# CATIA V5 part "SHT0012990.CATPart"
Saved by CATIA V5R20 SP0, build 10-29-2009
Part number: SHT0012990
Bounding box of the stored display mesh (mm): x 603.237 to 810.957, y -967.604 to -463.206, z 453.853 to 1311.371
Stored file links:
  C:\Users\gongbo\Desktop\设变_1\设变数据1-富生\主驾\不带侧板\SHT0012990.CATPart
  C:\Users\gongbo\Desktop\设变_1\设变数据1-富生\副驾不带腰托\高头枕\SHT0012236.CATPart

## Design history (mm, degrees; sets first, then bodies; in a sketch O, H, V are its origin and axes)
Body1 (main body)
Body2 "SHT0012990_AllCATPart.1\\头枕主体管\\零件几何体"
  Solid1: solid without history
Body3 "SHT0012990_AllCATPart.1\\靠背钢管上横骨架\\零件几何体"
  Solid2 "实体.1": solid without history
Body4 "SHT0012990_AllCATPart.1\\靠背下支撑管\\零件几何体"
  Solid3 "实体.1": solid without history
Body5 "SHT0012990_AllCATPart.1\\靠背支撑板条1\\零件几何体"
  Solid4 "实体.1": solid without history
Body6 "SHT0012990_AllCATPart.1\\支撑框线1\\零件几何体"
  Solid5 "实体.1": solid without history
Body7 "SHT0012990_AllCATPart.1\\腰托上固定片1.1\\零件几何体"
  Solid6 "实体.1": solid without history
Body8 "SHT0012990_AllCATPart.1\\腰托上固定片1.2\\零件几何体"
  Solid7 "实体.1": solid without history
Body9 "SHT0012990_AllCATPart.1\\腰托下固定片2.1\\零件几何体"
  Solid8 "实体.1": solid without history
Body10 "SHT0012990_AllCATPart.1\\腰托下固定片2.2\\零件几何体"
  Solid9 "实体.1": solid without history
Body11 "SHT0012990_AllCATPart.1\\旋转轴固定板.1\\旋转轴固定板"
  Solid10 "实体.1": solid without history
Body12 "SHT0012990_AllCATPart.1\\侧翼左侧泡沫支撑钢丝\\零件几何体"
  Solid11 "实体.1": solid without history
Body13 "SHT0012990_AllCATPart.1\\侧翼右侧泡沫支撑钢丝\\零件几何体"
  Solid12 "实体.1": solid without history
Body14 "SHT0012990_AllCATPart.1\\靠背主体管焊接总成\\靠背主体管.1\\零件几何体"
  Solid13 "实体.1": solid without history
Body15 "SHT0012990_AllCATPart.1\\靠背主体管焊接总成\\靠背骨架内衬管.2\\零件几何体"
  Solid14 "实体.1": solid without history
Body16 "SHT0012990_AllCATPart.1\\靠背主体管焊接总成\\靠背骨架内衬管.1\\零件几何体"
  Solid15 "实体.1": solid without history
Body17 "SHT0012990_AllCATPart.1\\靠背主体管焊接总成\\焊接六角螺母.1\\PartBody"
  Solid16 "实体.1": solid without history
Body18 "SHT0012990_AllCATPart.1\\靠背主体管焊接总成\\焊接六角螺母.2\\PartBody"
  Solid17 "实体.1": solid without history
Body19 "SHT0012990_AllCATPart.1\\靠背主体管焊接总成\\焊接六角螺母.3\\PartBody"
  Solid18 "实体.1": solid without history
Body20 "SHT0012990_AllCATPart.1\\靠背主体管焊接总成\\焊接六角螺母.4\\PartBody"
  Solid19 "实体.1": solid without history
Body21 "零件1.1\\sht0012236.1\\SHT0012224_AllCATPart.1\\几何体.39"
  Solid20 "实体.1": solid without history
Body22 "ASSY-fujiaditouzhen(wuyaotuo)_AllCATPart.1\\SHT0010244-1.1\\头枕横衬板\\H4 升级副驾.1\\副驾背总成\\H4 升级靠背总成_AllCATPart.1\\靠背骨架总成.1\\头枕盒\\横梁.2"
  Solid21: solid without history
